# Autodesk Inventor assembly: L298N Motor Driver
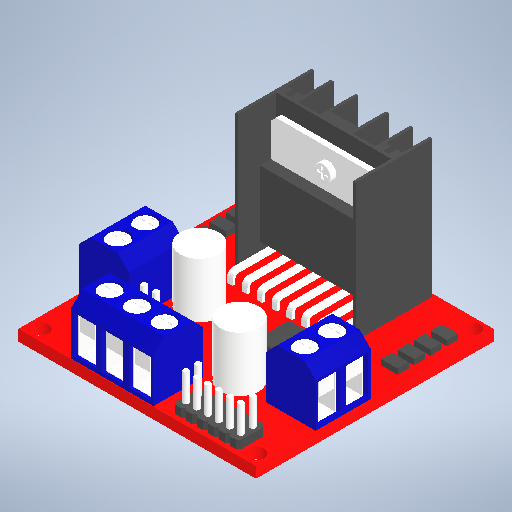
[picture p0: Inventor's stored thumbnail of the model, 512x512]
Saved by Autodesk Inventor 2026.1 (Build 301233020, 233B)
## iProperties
Created: 2025-07
Part Number: L298N Motor Driver
Document SubType Name: Assembly
Designer: hp
Title: L298N Motor Driver.step
Sending System: Autodesk Translation Framework v14.10.0.0
Preprocessor: ST-DEVELOPER v20.1
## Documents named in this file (4)
- C:\Users\hp\Documents\Inventor\DOM1_CartesianRobot\L298N Motor Driver.iam
- C:\Users\hp\Downloads\L298N Motor Driver\L298N Motor Driver\Pcb.ipt
- C:\Users\hp\Downloads\L298N Motor Driver\L298N Motor Driver\Pengunci.ipt
- C:\Users\hp\Downloads\L298N Motor Driver\L298N Motor Driver\Pengunci 2.ipt
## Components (4 placed, 3 different names)
1. Pcb:1
2. Pengunci:1
3. Pengunci 2:1
4. Pengunci:2
